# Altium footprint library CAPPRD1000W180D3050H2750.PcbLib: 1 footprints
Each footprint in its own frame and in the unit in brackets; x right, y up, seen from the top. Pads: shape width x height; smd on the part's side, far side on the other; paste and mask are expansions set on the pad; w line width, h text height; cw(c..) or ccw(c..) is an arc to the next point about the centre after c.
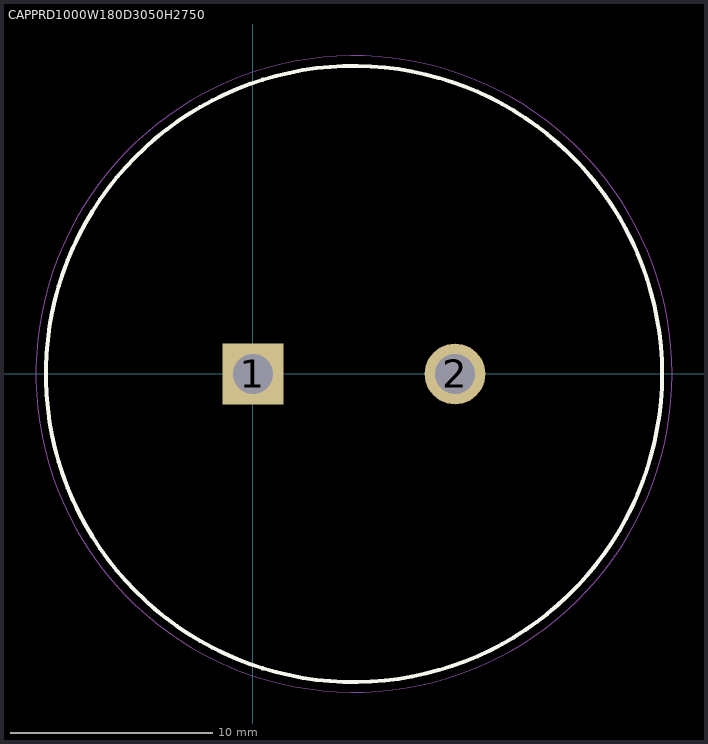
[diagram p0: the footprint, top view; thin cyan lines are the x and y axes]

## CAPPRD1000W180D3050H2750 [mm]
pads (2):
  rect 3x3 / inner round 3 / far side rect 3x3 hole 2: 1(0,0)
  round 3 hole 2: 2(10,0)
Top Overlay:
  circle w0.2: c5,0 r15.25
Mechanical 15:
  circle w0.1: c5,0 r15.25
Mechanical 20:
  circle w0.05: c5,0 r15.75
